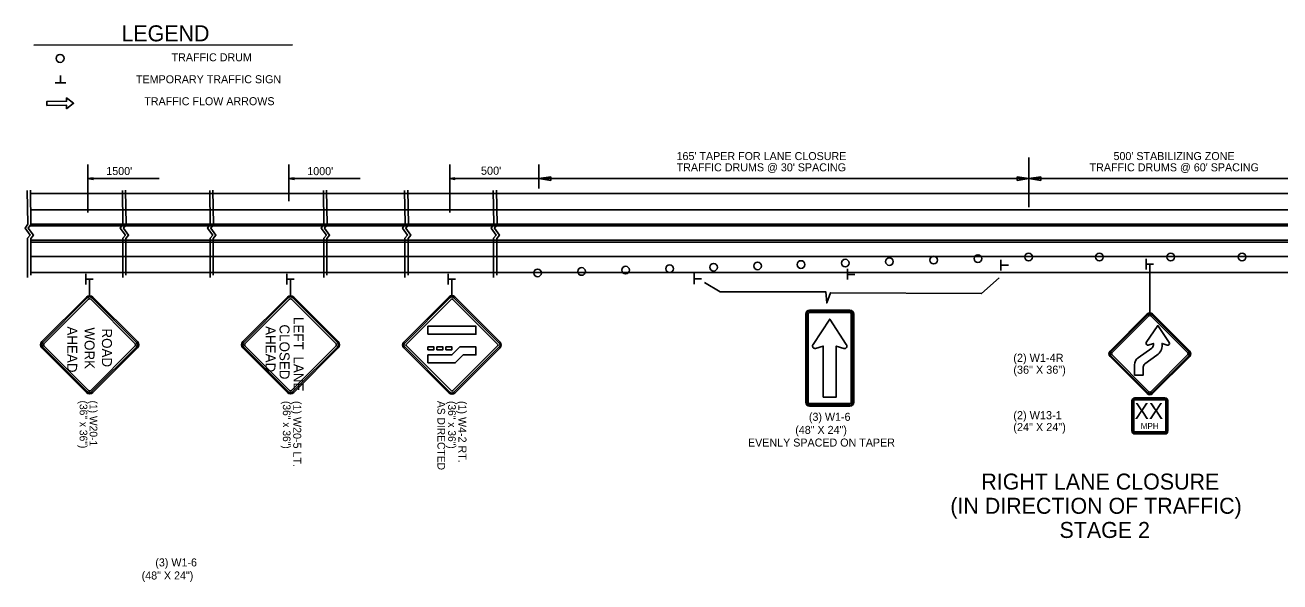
# Model space of a CAD drawing. Extents: x 1930579 to 1937984, y 596452 to 597630.
# Drawn here: x 1936489 to 1937430, y 597199 to 597617 of the extents above; entities that cross this region are included whole.
import ezdxf

# ---------------------------------------------------------------- set-up
doc = ezdxf.new("R2010")
doc.units = 0
for name, color, linetype in [('Default', 7, 'Continuous'), ('P_TC_Signs_Permanent', 7, 'Continuous'), ('P_TC_Signs_Temporary', 7, 'Continuous'), ('R_Border', 7, 'Continuous'), ('R_MOT', 7, 'Continuous')]:
    doc.layers.add(name, color=color, linetype=linetype)

msp = doc.modelspace()

# ---------------------------------------------------------------- linework, layer by layer
at = {"layer": 'Default'}
for p, q in [((1937241.46, 597517.31), (1937241.46, 597480.01)), ((1936536.26, 597511.96), (1936536.26, 597476.04)), ((1936686.9, 597511.96), (1936686.9, 597484.57)), ((1936807.47, 597511.96), (1936807.47, 597476.04)), ((1936874.25, 597511.96), (1936874.25, 597493.95)), ((1936540.09, 597502), (1936536.26, 597501.43)), ((1936536.26, 597501.43), (1936589.49, 597501.43)), ((1936540.09, 597500.85), (1936536.26, 597501.43)), ((1936540.09, 597501.91), (1936536.9, 597501.43)), ((1936540.09, 597500.95), (1936536.9, 597501.43)), ((1936540.09, 597501.81), (1936537.56, 597501.43)), ((1936540.09, 597501.05), (1936537.56, 597501.43)), ((1936540.09, 597501.71), (1936538.2, 597501.43)), ((1936540.09, 597501.14), (1936538.2, 597501.43)), ((1936540.09, 597501.62), (1936538.84, 597501.43)), ((1936540.09, 597501.24), (1936538.84, 597501.43)), ((1936540.09, 597501.52), (1936539.48, 597501.43)), ((1936540.09, 597501.34), (1936539.48, 597501.43)), ((1936540.09, 597500.85), (1936540.09, 597502)), ((1936690.72, 597502), (1936686.9, 597501.43)), ((1936686.9, 597501.43), (1936740.13, 597501.43)), ((1936690.72, 597500.85), (1936686.9, 597501.43)), ((1936690.72, 597501.91), (1936687.54, 597501.43)), ((1936690.72, 597500.95), (1936687.54, 597501.43)), ((1936690.72, 597501.81), (1936688.2, 597501.43)), ((1936690.72, 597501.05), (1936688.2, 597501.43)), ((1936690.72, 597501.71), (1936688.83, 597501.43)), ((1936690.72, 597501.14), (1936688.83, 597501.43)), ((1936690.72, 597501.62), (1936689.48, 597501.43)), ((1936690.72, 597501.24), (1936689.48, 597501.43)), ((1936690.72, 597501.52), (1936690.12, 597501.43)), ((1936690.72, 597501.34), (1936690.12, 597501.43)), ((1936690.72, 597500.85), (1936690.72, 597502)), ((1936811.29, 597502), (1936807.47, 597501.43)), ((1936807.47, 597501.43), (1936874.25, 597501.43)), ((1936811.29, 597500.85), (1936807.47, 597501.43)), ((1936811.29, 597501.91), (1936808.1, 597501.43)), ((1936811.29, 597500.95), (1936808.1, 597501.43)), ((1936811.29, 597501.81), (1936808.76, 597501.43)), ((1936811.29, 597501.05), (1936808.76, 597501.43)), ((1936811.29, 597501.71), (1936809.4, 597501.43)), ((1936811.29, 597501.14), (1936809.4, 597501.43)), ((1936811.29, 597501.62), (1936810.05, 597501.43)), ((1936811.29, 597501.24), (1936810.05, 597501.43)), ((1936811.29, 597501.52), (1936810.69, 597501.43)), ((1936811.29, 597501.34), (1936810.69, 597501.43)), ((1936811.29, 597500.85), (1936811.29, 597502)), ((1936874.25, 597501.43), (1936883.11, 597502.76)), ((1937241.46, 597501.43), (1936874.25, 597501.43)), ((1936883.11, 597500.1), (1936874.25, 597501.43)), ((1936883.11, 597502.76), (1936883.11, 597500.1)), ((1937232.6, 597500.1), (1937232.6, 597502.76)), ((1937232.6, 597502.76), (1937241.46, 597501.43)), ((1937241.46, 597501.43), (1937232.6, 597500.1)), ((1937241.46, 597501.43), (1937250.33, 597502.76)), ((1937493.2, 597501.43), (1937241.46, 597501.43)), ((1937250.33, 597500.1), (1937241.46, 597501.43)), ((1937250.33, 597502.76), (1937250.33, 597500.1)), ((1937493.2, 597490.19), (1936493.11, 597490.19)), ((1937493.2, 597478.19), (1936493.3, 597478.19)), ((1937493.2, 597466.02), (1936492.72, 597466.02)), ((1937493.2, 597467.4), (1936493.46, 597467.4)), ((1937493.2, 597455.23), (1936493.31, 597455.23)), ((1937493.2, 597453.85), (1936493.31, 597453.85)), ((1937493.2, 597443.19), (1936493.31, 597443.19)), ((1937220.47, 597432.53), (1937220.47, 597440.51)), ((1937329.26, 597433.42), (1937329.26, 597441.4)), ((1937329.38, 597437.39), (1937334.82, 597437.39)), ((1937493.2, 597431.19), (1936493.31, 597431.19)), ((1936534.64, 597422.09), (1936534.64, 597430.07)), ((1936685.22, 597422.09), (1936685.22, 597430.07)), ((1936806.18, 597422.09), (1936806.18, 597430.07)), ((1936990.55, 597422.26), (1936990.55, 597430.24)), ((1937105.51, 597425.75), (1937105.51, 597433.73)), ((1937105.63, 597429.72), (1937111.08, 597429.72)), ((1937220.59, 597436.5), (1937226.04, 597436.5)), ((1936534.76, 597426.06), (1936540.21, 597426.06)), ((1936685.34, 597426.06), (1936690.79, 597426.06)), ((1936806.3, 597426.05), (1936811.75, 597426.05)), ((1936990.67, 597426.23), (1936996.12, 597426.23))]:
    msp.add_line(p, q, dxfattribs=at)
for points in [[(1936490.68, 597492.48), (1936491.07, 597467.24), (1936489.12, 597464.34), (1936492.91, 597459.14), (1936490.92, 597456.74), (1936490.91, 597427.4)], [(1936493.08, 597492.71), (1936493.46, 597467.14), (1936491.52, 597464.24), (1936495.31, 597459.04), (1936493.31, 597456.64), (1936493.31, 597429.08)], [(1936562.05, 597492.48), (1936562.43, 597467.24), (1936560.48, 597464.34), (1936564.28, 597459.14), (1936562.28, 597456.74), (1936562.27, 597427.4)], [(1936564.44, 597492.71), (1936564.83, 597467.14), (1936562.88, 597464.24), (1936566.68, 597459.04), (1936564.68, 597456.64), (1936564.67, 597429.08)], [(1936627.49, 597492.48), (1936627.87, 597467.24), (1936625.92, 597464.34), (1936629.72, 597459.14), (1936627.72, 597456.74), (1936627.72, 597427.4)], [(1936629.88, 597492.71), (1936630.27, 597467.14), (1936628.32, 597464.24), (1936632.12, 597459.04), (1936630.12, 597456.64), (1936630.12, 597429.08)], [(1936712.68, 597492.48), (1936713.07, 597467.24), (1936711.12, 597464.34), (1936714.91, 597459.14), (1936712.92, 597456.74), (1936712.91, 597427.4)], [(1936715.08, 597492.71), (1936715.46, 597467.14), (1936713.52, 597464.24), (1936717.31, 597459.04), (1936715.31, 597456.64), (1936715.31, 597429.08)], [(1936773.57, 597492.48), (1936773.95, 597467.24), (1936772, 597464.34), (1936775.8, 597459.14), (1936773.8, 597456.74), (1936773.79, 597427.4)], [(1936775.96, 597492.71), (1936776.35, 597467.14), (1936774.4, 597464.24), (1936778.2, 597459.04), (1936776.2, 597456.64), (1936776.19, 597429.08)], [(1936840.02, 597492.48), (1936840.41, 597467.24), (1936838.46, 597464.34), (1936842.26, 597459.14), (1936840.26, 597456.74), (1936840.25, 597427.4)], [(1936842.42, 597492.71), (1936842.8, 597467.14), (1936840.86, 597464.24), (1936844.65, 597459.04), (1936842.65, 597456.64), (1936842.65, 597429.08)]]:
    msp.add_lwpolyline(points, dxfattribs=at)
for centre, radius in [((1936515.36, 597591.57), 3), ((1937005.1, 597435), 2.87), ((1937038.09, 597436.04), 2.87), ((1937070.62, 597437.08), 2.87), ((1937103.77, 597438.18), 2.87), ((1937136.93, 597439.28), 2.87), ((1937170.08, 597440.38), 2.87), ((1937203.23, 597441.48), 2.87), ((1937241.17, 597442.71), 2.87), ((1937294.26, 597442.71), 2.87), ((1937347.73, 597442.71), 2.87), ((1937401.2, 597442.71), 2.87), ((1936873.17, 597430.82), 2.87), ((1936906.15, 597431.86), 2.87), ((1936939.14, 597432.91), 2.87), ((1936972.12, 597433.95), 2.87)]:
    msp.add_circle(centre, radius, dxfattribs=at)
at = {"layer": 'P_TC_Signs_Permanent'}
for p, q in [((1936772.96, 597378.89), (1936806.9, 597412.83)), ((1937074.16, 597400.12), (1937074.16, 597333.75)), ((1937074.91, 597400.12), (1937074.91, 597333.75)), ((1937076.03, 597400.12), (1937076.03, 597333.75)), ((1937107.35, 597402.94), (1937076.97, 597402.94)), ((1937107.35, 597402.19), (1937076.97, 597402.19)), ((1937107.35, 597401.06), (1937076.97, 597401.06)), ((1937108.28, 597333.75), (1937108.28, 597400.12)), ((1937109.41, 597333.75), (1937109.41, 597400.12)), ((1937110.16, 597333.75), (1937110.16, 597400.12)), ((1937302.27, 597372.17), (1937330.11, 597400.02)), ((1937334.09, 597400.02), (1937361.93, 597372.17)), ((1936827.02, 597384.81), (1936827.02, 597390.81)), ((1937302.8, 597371.64), (1937330.64, 597399.49)), ((1937331.44, 597398.69), (1937303.6, 597370.85)), ((1937360.61, 597370.85), (1937332.76, 597398.69)), ((1937333.56, 597399.49), (1937361.4, 597371.64)), ((1936806.9, 597340.7), (1936772.96, 597374.65)), ((1936845.09, 597374.65), (1936811.15, 597340.7)), ((1937323.34, 597367.11), (1937333.56, 597374.47)), ((1937330.11, 597340.35), (1937302.27, 597368.2)), ((1937330.64, 597340.88), (1937302.8, 597368.73)), ((1937303.6, 597369.52), (1937331.44, 597341.68)), ((1937337.39, 597369.14), (1937328.35, 597362.62)), ((1937332.76, 597341.68), (1937360.61, 597369.52)), ((1937361.4, 597368.73), (1937333.56, 597340.88)), ((1937361.93, 597368.2), (1937334.09, 597340.35)), ((1937318.6, 597334.81), (1937318.6, 597312.31)), ((1937319.16, 597334.81), (1937319.16, 597312.31)), ((1937320.1, 597334.81), (1937320.1, 597312.31)), ((1937343.35, 597337.06), (1937320.85, 597337.06)), ((1937343.35, 597336.49), (1937320.85, 597336.49)), ((1937343.35, 597335.56), (1937320.85, 597335.56)), ((1937344.1, 597312.31), (1937344.1, 597334.81)), ((1937345.04, 597312.31), (1937345.04, 597334.81)), ((1937345.6, 597312.31), (1937345.6, 597334.81)), ((1937076.97, 597332.81), (1937107.35, 597332.81)), ((1937076.97, 597331.69), (1937107.35, 597331.69)), ((1937076.97, 597330.94), (1937107.35, 597330.94)), ((1937320.85, 597311.56), (1937343.35, 597311.56)), ((1937320.85, 597310.62), (1937343.35, 597310.62)), ((1937320.85, 597310.06), (1937343.35, 597310.06))]:
    msp.add_line(p, q, dxfattribs=at)
for points in [[(1936807.54, 597412.19), (1936773.6, 597378.25)], [(1936774.66, 597377.19), (1936808.6, 597411.13)], [(1936809.45, 597411.13), (1936843.39, 597377.19)], [(1936844.45, 597378.25), (1936810.51, 597412.19)], [(1936811.15, 597412.83), (1936828.12, 597395.86), (1936845.09, 597378.89)], [(1937104.6, 597377.19), (1937092.16, 597396.19), (1937079.75, 597377.18)], [(1937329.42, 597378.71), (1937338.01, 597391.28), (1937346.59, 597378.71)], [(1936773.6, 597375.28), (1936807.54, 597341.34)], [(1936808.6, 597342.4), (1936774.66, 597376.34)], [(1936843.39, 597376.34), (1936809.45, 597342.4)], [(1936810.51, 597341.34), (1936844.45, 597375.28)], [(1937081.52, 597374.23), (1937087.28, 597375.95), (1937087.28, 597337.69), (1937097.03, 597337.69), (1937097.03, 597375.95), (1937102.78, 597374.2)], [(1937334.73, 597376.75), (1937334.73, 597377.94), (1937330.91, 597376.72)], [(1937345.11, 597376.72), (1937341.29, 597377.94), (1937341.29, 597376.75)], [(1937327.18, 597360.34), (1937327.18, 597354.25), (1937320.62, 597354.25), (1937320.62, 597361.78)]]:
    msp.add_lwpolyline(points, dxfattribs=at)
for points in [[(1936791.02, 597384.81), (1936791.02, 597390.81), (1936827.02, 597390.81), (1936827.02, 597384.81)], [(1936791.02, 597373.17), (1936791.02, 597375.27), (1936795.52, 597375.27), (1936795.52, 597373.17)], [(1936791.02, 597363.27), (1936791.02, 597369.27), (1936809.02, 597369.27), (1936815.02, 597375.27), (1936827.02, 597375.27), (1936827.02, 597369.27), (1936817.51, 597369.27), (1936811.51, 597363.27)], [(1936797.77, 597373.17), (1936797.77, 597375.27), (1936802.27, 597375.27), (1936802.27, 597373.17)], [(1936804.52, 597373.17), (1936804.52, 597375.27), (1936809.02, 597375.27), (1936809.02, 597373.17)]]:
    msp.add_lwpolyline(points, close=True, dxfattribs=at)
for centre, radius, start, end in [((1936809.02, 597410.71), 3, 45, 135), ((1936809.02, 597410.71), 2.1, 45, 135), ((1936809.02, 597410.71), 0.6, 45, 135), ((1937076.97, 597400.12), 2.81, 90, 180), ((1937076.97, 597400.12), 2.06, 90, 180), ((1937076.97, 597400.12), 0.938, 90, 180), ((1937107.35, 597400.12), 2.81, 360, 90), ((1937107.35, 597400.12), 2.06, 360, 90), ((1937107.35, 597400.12), 0.938, 360, 90), ((1937332.1, 597398.03), 2.81, 45, 135), ((1937332.1, 597398.03), 2.06, 45, 135), ((1937332.1, 597398.03), 0.937, 45, 135), ((1936775.08, 597376.77), 3, 135, 225), ((1936775.08, 597376.77), 2.1, 135, 225), ((1936775.08, 597376.77), 0.6, 135, 225), ((1936842.97, 597376.77), 0.6, 315, 45), ((1936842.97, 597376.77), 2.1, 315, 45), ((1936842.97, 597376.77), 3, 315, 45), ((1937081.04, 597375.93), 1.76, 146.59943, 285.96908), ((1937016.95, 597418.19), 75, 326.59943, 326.85697), ((1937103.28, 597375.93), 1.8, 254.03093, 33.47548), ((1937167.34, 597418.29), 75, 213.2286, 213.47548), ((1937304.26, 597370.18), 2.81, 135, 225), ((1937304.26, 597370.18), 2.06, 135, 225), ((1937330.51, 597377.97), 1.31, 145.6763, 287.81282), ((1937331.91, 597376.75), 2.81, 305.77329, 0), ((1937331.91, 597376.75), 9.38, 305.77329, 0), ((1937345.51, 597377.97), 1.31, 252.18718, 34.3237), ((1937359.94, 597370.18), 2.06, 315, 45), ((1937359.94, 597370.18), 2.81, 315, 45), ((1937304.26, 597370.18), 0.938, 135, 225), ((1937327.18, 597361.78), 6.56, 125.77329, 180), ((1937329.99, 597360.34), 2.81, 125.77329, 180), ((1937359.94, 597370.18), 0.937, 315, 45), ((1936809.02, 597342.83), 3, 225, 315), ((1936809.02, 597342.83), 2.1, 225, 315), ((1936809.02, 597342.83), 0.6, 225, 315), ((1937320.85, 597334.81), 2.25, 90, 180), ((1937320.85, 597334.81), 1.69, 90, 180), ((1937320.85, 597334.81), 0.75, 90, 180), ((1937332.1, 597342.34), 2.81, 225, 315), ((1937332.1, 597342.34), 2.06, 225, 315), ((1937332.1, 597342.34), 0.937, 225, 315), ((1937343.35, 597334.81), 2.25, 360, 90), ((1937343.35, 597334.81), 1.69, 360, 90), ((1937343.35, 597334.81), 0.75, 360, 90), ((1937076.97, 597333.75), 2.81, 180, 270), ((1937076.97, 597333.75), 2.06, 180, 270), ((1937076.97, 597333.75), 0.937, 180, 270), ((1937107.35, 597333.75), 2.81, 270, 360), ((1937107.35, 597333.75), 2.06, 270, 360), ((1937107.35, 597333.75), 0.938, 270, 360), ((1937320.85, 597312.31), 2.25, 180, 270), ((1937320.85, 597312.31), 1.69, 180, 270), ((1937320.85, 597312.31), 0.75, 180, 270), ((1937343.35, 597312.31), 2.25, 270, 360), ((1937343.35, 597312.31), 1.69, 270, 360), ((1937343.35, 597312.31), 0.75, 270, 360)]:
    msp.add_arc(centre, radius, start, end, dxfattribs=at)
at = {"layer": 'P_TC_Signs_Temporary'}
for p, q in [((1936501.69, 597379.31), (1936535.1, 597412.72)), ((1936502.35, 597378.65), (1936535.76, 597412.06)), ((1936503.28, 597377.72), (1936536.69, 597411.13)), ((1936538.28, 597411.13), (1936571.69, 597377.72)), ((1936539.21, 597412.06), (1936572.62, 597378.65)), ((1936539.87, 597412.72), (1936573.28, 597379.31)), ((1936652.27, 597379.31), (1936685.68, 597412.72)), ((1936652.93, 597378.65), (1936686.34, 597412.06)), ((1936653.86, 597377.72), (1936687.27, 597411.13)), ((1936688.86, 597411.13), (1936722.27, 597377.72)), ((1936689.79, 597412.06), (1936723.2, 597378.65)), ((1936690.45, 597412.72), (1936723.86, 597379.31)), ((1936535.1, 597341.12), (1936501.69, 597374.54)), ((1936535.76, 597341.79), (1936502.35, 597375.2)), ((1936536.69, 597342.72), (1936503.28, 597376.13)), ((1936571.69, 597376.13), (1936538.28, 597342.72)), ((1936572.62, 597375.2), (1936539.21, 597341.79)), ((1936573.28, 597374.54), (1936539.87, 597341.12)), ((1936685.68, 597341.12), (1936652.27, 597374.54)), ((1936686.34, 597341.79), (1936652.93, 597375.2)), ((1936687.27, 597342.72), (1936653.86, 597376.13)), ((1936722.27, 597376.13), (1936688.86, 597342.72)), ((1936723.2, 597375.2), (1936689.79, 597341.79)), ((1936723.86, 597374.54), (1936690.45, 597341.12))]:
    msp.add_line(p, q, dxfattribs=at)
for centre, radius, start, end in [((1936537.49, 597410.33), 3.38, 45, 135), ((1936537.49, 597410.33), 2.44, 45, 135), ((1936537.49, 597410.33), 1.12, 45, 135), ((1936688.06, 597410.33), 3.38, 45, 135), ((1936688.06, 597410.33), 2.44, 45, 135), ((1936688.06, 597410.33), 1.12, 45, 135), ((1936504.07, 597376.92), 3.38, 135, 225), ((1936504.07, 597376.92), 2.44, 135, 225), ((1936504.07, 597376.92), 1.13, 135, 225), ((1936570.9, 597376.92), 1.13, 315, 45), ((1936570.9, 597376.92), 2.44, 315, 45), ((1936570.9, 597376.92), 3.38, 315, 45), ((1936654.65, 597376.92), 3.38, 135, 225), ((1936654.65, 597376.92), 2.44, 135, 225), ((1936654.65, 597376.92), 1.13, 135, 225), ((1936721.47, 597376.92), 1.13, 315, 45), ((1936721.47, 597376.92), 2.44, 315, 45), ((1936721.47, 597376.92), 3.38, 315, 45), ((1936537.49, 597343.51), 3.38, 225, 315), ((1936537.49, 597343.51), 2.44, 225, 315), ((1936537.49, 597343.51), 1.12, 225, 315), ((1936688.06, 597343.51), 3.38, 225, 315), ((1936688.06, 597343.51), 2.44, 225, 315), ((1936688.06, 597343.51), 1.12, 225, 315)]:
    msp.add_arc(centre, radius, start, end, dxfattribs=at)
at = {"layer": 'R_Border'}
for p, q in [((1936495.59, 597601.6), (1936689.5, 597601.73)), ((1936515.74, 597573.4), (1936515.74, 597578.86)), ((1936519.72, 597573.29), (1936511.72, 597573.28)), ((1937332.1, 597437.39), (1937332.1, 597400.84)), ((1936537.49, 597426.06), (1936537.49, 597413.71)), ((1936688.06, 597426.06), (1936688.06, 597413.71)), ((1936809.02, 597426.05), (1936809.02, 597413.71))]:
    msp.add_line(p, q, dxfattribs=at)
msp.add_lwpolyline([(1936998.23, 597423.61), (1937010.04, 597416.66), (1937089.24, 597416.66), (1937089.94, 597408.32), (1937092.72, 597415.97), (1937205.97, 597415.27), (1937219.17, 597427.09)], dxfattribs=at)
at = {"layer": 'R_MOT'}
msp.add_lwpolyline([(1936520.24, 597553.89), (1936525.43, 597557.89), (1936520.23, 597561.89), (1936520.23, 597559.39), (1936505.52, 597559.38), (1936505.52, 597556.38), (1936520.24, 597556.39)], close=True, dxfattribs=at)

# ---------------------------------------------------------------- texts
at = {"layer": 'Default'}
for s, height, p in [("TRAFFIC DRUMS @ 30' SPACING", 6, (1936977.42, 597506.93)), ("165' TAPER FOR LANE CLOSURE", 6, (1936977.35, 597515.36)), ("TRAFFIC DRUMS @ 60' SPACING", 6, (1937286.9, 597506.93)), ("500' STABILIZING ZONE", 6, (1937304.83, 597515.36)), ("1500'", 6, (1936549.98, 597504.15)), ("1000'", 6, (1936700.62, 597504.06)), ("500'", 6.12, (1936830.76, 597504.34)), ('RIGHT LANE CLOSURE', 12, (1937205.79, 597268.37)), ('(IN DIRECTION OF TRAFFIC)', 12, (1937182.54, 597250.25)), ('STAGE 2', 12, (1937264.37, 597232.13))]:
    msp.add_text(s, height=height, rotation=360, dxfattribs=at).set_placement(p)
at = {"layer": 'P_TC_Signs_Permanent'}
for s, height, p in [('XX', 12, (1937320.64, 597321.31)), ('MPH', 4.5, (1937325.27, 597313.81))]:
    msp.add_text(s, height=height, rotation=360, dxfattribs=at).set_placement(p)
at = {"layer": 'P_TC_Signs_Temporary'}
for s, p in [(' AHEAD ', (1936520.65, 597393.46)), (' AHEAD ', (1936669.31, 597393.69)), ('CLOSED', (1936679.81, 597392.17)), ('LEFT\u2002LANE', (1936690.31, 597397.72)), ('WORK', (1936533.68, 597389.91)), (' ROAD ', (1936546.7, 597391.94))]:
    msp.add_text(s, height=7.5, rotation=270, dxfattribs=at).set_placement(p)
at = {"layer": 'R_Border'}
for s, height, rotation, p in [('LEGEND', 12, 0.03878, (1936561.32, 597604.33)), ('TRAFFIC DRUM', 6, 0.03876, (1936598.9, 597589.37)), ('TEMPORARY TRAFFIC SIGN', 6, 0.03876, (1936572.23, 597572.89)), ('TRAFFIC FLOW ARROWS', 6, 0.03876, (1936578.44, 597556.43)), ('(2) W1-4R', 6.099, 360, (1937229.77, 597364.09)), ('(36" X 36")', 6.0988, 360, (1937229.77, 597355.21)), ('(36" x 36")', 5.76, 270, (1936530, 597335.14)), ('(1) W20-1', 5.76, 270, (1936537.49, 597335.14)), ('(36" x 36")', 5.76, 270, (1936682.3, 597334.83)), ('(1) W20-5 LT.', 6, 270, (1936690.07, 597334.83)), ('AS DIRECTED ', 5.76, 270, (1936798.14, 597334.83)), ('(36" x 36")', 5.76, 270, (1936806.14, 597334.83)), ('(1) W4-2 RT.', 6, 270, (1936813.91, 597334.83)), ('(3) W1-6', 6, 0.00754, (1937076.54, 597319.93)), ('(2) W13-1', 6.099, 360, (1937229.77, 597321.07)), ('(48" X 24")', 6, 0.00754, (1937066.32, 597310.13)), ('(24" X 24")', 6.0988, 360, (1937229.77, 597312.19)), ('EVENLY SPACED ON TAPER', 6, 0.00754, (1937030.91, 597300.64)), ('(3) W1-6', 6, 0.00754, (1936586.71, 597210.8)), ('(48" X 24")', 6, 0.00754, (1936576.48, 597201))]:
    msp.add_text(s, height=height, rotation=rotation, dxfattribs=at).set_placement(p)

doc.saveas('drawing.dxf')
